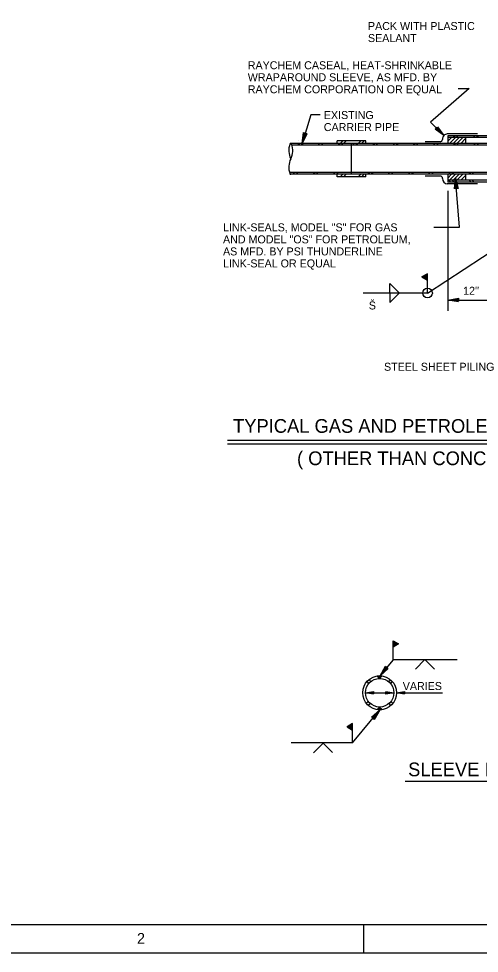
# Model space of a CAD drawing. Extents: x 22422.9 to 22498.9, y 22369.6 to 22415.
# Drawn here: x 22455.11 to 22465.87, y 22369.62 to 22391.43 of the extents above; entities that cross this region are included whole.
import ezdxf

# ---------------------------------------------------------------- set-up
doc = ezdxf.new("R2010")
doc.units = 0
for name, color, linetype in [('Level 1', 7, 'Continuous'), ('Level 10', 7, 'Continuous'), ('Level 2', 7, 'Continuous'), ('Level 3', 7, 'Continuous'), ('Level 4', 7, 'Continuous'), ('Level 7', 7, 'Continuous'), ('Level 8', 7, 'Continuous'), ('Level 9', 7, 'Continuous')]:
    doc.layers.add(name, color=color, linetype=linetype)

msp = doc.modelspace()

# ---------------------------------------------------------------- linework, layer by layer
at = {"layer": 'Level 1'}
for p, q in [((22461.644, 22388.584), (22461.644, 22388.584)), ((22468.13, 22388.696), (22465.13, 22388.696)), ((22468.13, 22388.655), (22465.13, 22388.655)), ((22465.13, 22388.566), (22465.218, 22388.655)), ((22465.166, 22388.514), (22465.307, 22388.655)), ((22465.254, 22388.514), (22465.395, 22388.655)), ((22465.343, 22388.514), (22465.483, 22388.655)), ((22465.431, 22388.514), (22465.546, 22388.629)), ((22465.13, 22387.707), (22465.218, 22387.795)), ((22465.166, 22387.655), (22465.307, 22387.795)), ((22465.254, 22387.655), (22465.395, 22387.795)), ((22465.343, 22387.655), (22465.483, 22387.795)), ((22465.431, 22387.655), (22465.546, 22387.77)), ((22468.13, 22387.655), (22465.13, 22387.655)), ((22468.13, 22387.613), (22465.13, 22387.613)), ((22465.361, 22387.569), (22465.361, 22387.569)), ((22465.13, 22387.412), (22465.13, 22384.613)), ((22465.13, 22384.861), (22466.128, 22384.861)), ((22463.594, 22376.152), (22463.594, 22376.152)), ((22463.287, 22375.919), (22463.243, 22375.964)), ((22463.332, 22375.962), (22463.288, 22376.007)), ((22463.55, 22376.098), (22463.55, 22376.098)), ((22463.747, 22375.96), (22463.791, 22376.005)), ((22463.792, 22375.917), (22463.836, 22375.961)), ((22463.205, 22375.7), (22463.872, 22375.7)), ((22463.205, 22375.7), (22463.205, 22375.7)), ((22463.257, 22375.7), (22463.257, 22375.7)), ((22463.82, 22375.7), (22463.82, 22375.7)), ((22463.872, 22375.7), (22463.872, 22375.7)), ((22463.934, 22375.7), (22465.007, 22375.7)), ((22463.934, 22375.7), (22463.934, 22375.7)), ((22463.986, 22375.7), (22463.986, 22375.7)), ((22463.228, 22375.454), (22463.273, 22375.498)), ((22463.845, 22375.45), (22463.8, 22375.494)), ((22463.271, 22375.408), (22463.315, 22375.452)), ((22463.541, 22375.298), (22463.541, 22375.298)), ((22463.802, 22375.405), (22463.757, 22375.449)), ((22463.497, 22375.245), (22463.497, 22375.245))]:
    msp.add_line(p, q, dxfattribs=at)
msp.add_lwpolyline([(22440.26, 22414.965), (22498.927, 22414.965), (22498.927, 22369.621), (22440.26, 22369.621)], close=True, dxfattribs=at)
for points in [[(22463.392, 22375.669), (22463.205, 22375.7), (22463.392, 22375.731), (22463.392, 22375.678), (22463.257, 22375.7), (22463.384, 22375.721), (22463.384, 22375.687), (22463.307, 22375.7), (22463.376, 22375.711), (22463.376, 22375.697), (22463.359, 22375.7)], [(22463.685, 22375.731), (22463.872, 22375.7), (22463.685, 22375.669), (22463.685, 22375.722), (22463.82, 22375.7), (22463.693, 22375.679), (22463.693, 22375.713), (22463.77, 22375.7), (22463.701, 22375.689), (22463.701, 22375.703), (22463.718, 22375.7)], [(22464.121, 22375.669), (22463.934, 22375.7), (22464.121, 22375.731), (22464.121, 22375.678), (22463.986, 22375.7), (22464.113, 22375.721), (22464.113, 22375.687), (22464.036, 22375.7), (22464.105, 22375.711), (22464.105, 22375.697), (22464.088, 22375.7)]]:
    msp.add_lwpolyline(points, dxfattribs=at)
for centre, radius, start, end in [((22461.852, 22388.35), 0.436, 159.8064, 206.6071), ((22461.463, 22388.493), 0.0213, 20.1936, 159.8064), ((22461.074, 22388.35), 0.436, 333.3929, 20.1936), ((22461.852, 22387.96), 0.436, 153.3929, 200.1919), ((22461.463, 22387.817), 0.0213, 200.3155, 270)]:
    msp.add_arc(centre, radius, start, end, dxfattribs=at)
at = {"layer": 'Level 10'}
for p, q in [((22464.656, 22385.026), (22467.63, 22386.967)), ((22464.656, 22385.476), (22464.526, 22385.401)), ((22464.526, 22385.401), (22464.656, 22385.448)), ((22464.526, 22385.401), (22464.656, 22385.422)), ((22464.526, 22385.401), (22464.655, 22385.326)), ((22464.526, 22385.401), (22464.649, 22385.394)), ((22464.526, 22385.401), (22464.653, 22385.371)), ((22464.526, 22385.401), (22464.656, 22385.35)), ((22464.656, 22385.026), (22464.656, 22385.476)), ((22463.777, 22385.249), (22464.001, 22385.025)), ((22463.777, 22385.024), (22463.777, 22385.249)), ((22464.656, 22385.026), (22463.155, 22385.026)), ((22463.777, 22385.028), (22463.777, 22384.803)), ((22463.777, 22384.803), (22464.001, 22385.027)), ((22459.986, 22381.589), (22476.306, 22381.589)), ((22459.986, 22381.505), (22476.327, 22381.505)), ((22463.851, 22376.464), (22463.851, 22376.914)), ((22463.851, 22376.914), (22463.981, 22376.839)), ((22463.981, 22376.839), (22463.851, 22376.885)), ((22463.981, 22376.839), (22463.851, 22376.86)), ((22463.981, 22376.839), (22463.851, 22376.764)), ((22463.981, 22376.839), (22463.851, 22376.788)), ((22463.981, 22376.839), (22463.853, 22376.809)), ((22463.981, 22376.839), (22463.858, 22376.832)), ((22463.55, 22376.098), (22463.851, 22376.464)), ((22463.846, 22376.472), (22465.347, 22376.472)), ((22464.597, 22376.472), (22464.375, 22376.25)), ((22464.596, 22376.472), (22464.82, 22376.248)), ((22462.907, 22374.529), (22463.541, 22375.298)), ((22462.907, 22374.979), (22462.777, 22374.904)), ((22462.777, 22374.904), (22462.907, 22374.951)), ((22462.777, 22374.904), (22462.907, 22374.925)), ((22462.777, 22374.904), (22462.907, 22374.829)), ((22462.777, 22374.904), (22462.9, 22374.897)), ((22462.777, 22374.904), (22462.905, 22374.874)), ((22462.777, 22374.904), (22462.907, 22374.853)), ((22462.907, 22374.529), (22462.907, 22374.798)), ((22462.907, 22374.529), (22461.469, 22374.529)), ((22462.218, 22374.525), (22461.995, 22374.301)), ((22462.218, 22374.524), (22462.439, 22374.303)), ((22464.137, 22373.635), (22472.537, 22373.635)), ((22463.167, 22369.621), (22463.167, 22370.293))]:
    msp.add_line(p, q, dxfattribs=at)
for points in [[(22463.74, 22376.264), (22463.55, 22376.098), (22463.676, 22376.317), (22463.731, 22376.272), (22463.594, 22376.152), (22463.68, 22376.3), (22463.715, 22376.271), (22463.636, 22376.203), (22463.683, 22376.283), (22463.698, 22376.271), (22463.68, 22376.257)], [(22463.35, 22375.132), (22463.541, 22375.298), (22463.414, 22375.079), (22463.36, 22375.124), (22463.497, 22375.245), (22463.411, 22375.096), (22463.376, 22375.125), (22463.454, 22375.193), (22463.407, 22375.113), (22463.393, 22375.125), (22463.41, 22375.14)]]:
    msp.add_lwpolyline(points, dxfattribs=at)
msp.add_circle((22464.656, 22385.026), 0.113, dxfattribs=at)
at = {"layer": 'Level 2'}
for p, q in [((22465.628, 22389.797), (22464.728, 22389.011)), ((22465.369, 22389.797), (22465.628, 22389.797)), ((22464.728, 22389.011), (22465.038, 22388.7)), ((22462.546, 22388.514), (22462.546, 22388.577)), ((22463.213, 22388.577), (22462.546, 22388.577)), ((22463.213, 22388.514), (22463.213, 22388.577)), ((22465.13, 22388.696), (22465.13, 22388.514)), ((22465.546, 22388.655), (22465.546, 22388.514)), ((22468.13, 22388.514), (22461.463, 22388.514)), ((22468.13, 22388.472), (22461.492, 22388.472)), ((22462.88, 22387.795), (22462.88, 22388.514)), ((22468.13, 22387.837), (22461.434, 22387.837)), ((22468.13, 22387.795), (22461.464, 22387.795)), ((22462.546, 22387.733), (22462.546, 22387.795)), ((22463.213, 22387.733), (22462.546, 22387.733)), ((22463.213, 22387.733), (22463.213, 22387.795)), ((22465.13, 22387.795), (22465.13, 22387.613)), ((22465.546, 22387.795), (22465.546, 22387.655)), ((22463.538, 22376.034), (22463.48, 22376.092)), ((22463.538, 22376.034), (22463.596, 22376.092)), ((22463.538, 22375.367), (22463.48, 22375.309)), ((22463.538, 22375.367), (22463.596, 22375.309))]:
    msp.add_line(p, q, dxfattribs=at)
for points in [[(22462.151, 22389.185), (22461.932, 22389.185), (22461.726, 22388.517)], [(22464.891, 22388.906), (22465.038, 22388.7), (22464.832, 22388.848), (22464.882, 22388.898), (22464.989, 22388.75), (22464.849, 22388.85), (22464.881, 22388.882), (22464.942, 22388.797), (22464.866, 22388.851), (22464.88, 22388.865), (22464.893, 22388.846)], [(22461.839, 22388.743), (22461.726, 22388.517), (22461.76, 22388.767), (22461.828, 22388.746), (22461.747, 22388.583), (22461.77, 22388.753), (22461.813, 22388.74), (22461.766, 22388.647), (22461.779, 22388.739), (22461.797, 22388.733), (22461.787, 22388.713)], [(22464.801, 22386.562), (22465.4, 22386.562), (22465.309, 22387.709)], [(22465.287, 22387.457), (22465.309, 22387.709), (22465.37, 22387.464), (22465.299, 22387.458), (22465.314, 22387.64), (22465.356, 22387.473), (22465.31, 22387.47), (22465.32, 22387.574), (22465.342, 22387.483), (22465.323, 22387.482), (22465.325, 22387.504)], [(22465.379, 22384.82), (22465.13, 22384.861), (22465.379, 22384.903), (22465.379, 22384.832), (22465.199, 22384.861), (22465.368, 22384.889), (22465.368, 22384.844), (22465.266, 22384.861), (22465.358, 22384.876), (22465.358, 22384.857), (22465.335, 22384.861)], [(22463.481, 22376.091), (22463.595, 22376.091)], [(22463.492, 22376.08), (22463.585, 22376.08)], [(22463.502, 22376.07), (22463.575, 22376.07)], [(22463.512, 22376.059), (22463.564, 22376.059)], [(22463.523, 22376.049), (22463.554, 22376.049)], [(22463.533, 22376.039), (22463.543, 22376.039)], [(22463.488, 22375.317), (22463.588, 22375.317)], [(22463.499, 22375.327), (22463.578, 22375.327)], [(22463.5, 22375.306), (22463.578, 22375.306)], [(22463.509, 22375.338), (22463.567, 22375.338)], [(22463.519, 22375.348), (22463.557, 22375.348)], [(22463.53, 22375.359), (22463.547, 22375.359)]]:
    msp.add_lwpolyline(points, dxfattribs=at)
for radius in [0.396, 0.333]:
    msp.add_circle((22463.538, 22375.7), radius, dxfattribs=at)
at = {"layer": 'Level 3'}
for p, q in [((22463.538, 22376.034), (22463.538, 22376.034)), ((22463.538, 22375.7), (22463.538, 22375.7))]:
    msp.add_line(p, q, dxfattribs=at)
at = {"layer": 'Level 4'}
msp.add_line((22462.907, 22374.798), (22462.907, 22374.979), dxfattribs=at)
at = {"layer": 'Level 7'}
for p, q in [((22465.823, 22388.738), (22465.119, 22388.738)), ((22464.949, 22388.556), (22464.602, 22388.556)), ((22464.949, 22387.754), (22464.602, 22387.754)), ((22465.823, 22387.571), (22465.119, 22387.571)), ((22464.597, 22376.472), (22464.597, 22376.472)), ((22462.217, 22374.525), (22462.218, 22374.524))]:
    msp.add_line(p, q, dxfattribs=at)
for centre, radius, start, end in [((22464.949, 22388.611), 0.0555, 270, 0), ((22465.126, 22388.617), 0.121, 92.9001, 182.9001), ((22464.949, 22387.696), 0.0581, 0, 90), ((22465.126, 22387.689), 0.118, 177.036, 267.036)]:
    msp.add_arc(centre, radius, start, end, dxfattribs=at)
at = {"layer": 'Level 8'}
for p, q in [((22461.747, 22388.583), (22461.747, 22388.583)), ((22464.989, 22388.75), (22464.989, 22388.75)), ((22465.038, 22388.7), (22465.038, 22388.7)), ((22461.726, 22388.517), (22461.726, 22388.517)), ((22465.309, 22387.709), (22465.309, 22387.709)), ((22465.314, 22387.64), (22465.314, 22387.64)), ((22465.13, 22384.861), (22465.13, 22384.861)), ((22465.199, 22384.861), (22465.199, 22384.861))]:
    msp.add_line(p, q, dxfattribs=at)
for points in [[(22462.68, 22388.577), (22462.617, 22388.514)], [(22462.76, 22388.577), (22462.697, 22388.514)], [(22463.102, 22388.577), (22463.039, 22388.514)], [(22463.179, 22388.577), (22463.117, 22388.514)], [(22465.292, 22388.66), (22465.256, 22388.696)], [(22465.368, 22388.66), (22465.331, 22388.696)], [(22465.764, 22388.66), (22465.727, 22388.696)], [(22465.839, 22388.66), (22465.803, 22388.696)], [(22461.672, 22388.472), (22461.63, 22388.514)], [(22461.748, 22388.472), (22461.706, 22388.514)], [(22462.143, 22388.472), (22462.102, 22388.514)], [(22462.219, 22388.472), (22462.177, 22388.514)], [(22462.615, 22388.472), (22462.573, 22388.514)], [(22462.69, 22388.472), (22462.649, 22388.514)], [(22462.952, 22388.472), (22462.911, 22388.514)], [(22463.026, 22388.472), (22462.984, 22388.514)], [(22463.422, 22388.472), (22463.38, 22388.514)], [(22463.498, 22388.472), (22463.456, 22388.514)], [(22463.894, 22388.472), (22463.852, 22388.514)], [(22463.969, 22388.472), (22463.927, 22388.514)], [(22464.365, 22388.472), (22464.323, 22388.514)], [(22464.44, 22388.472), (22464.399, 22388.514)], [(22464.836, 22388.472), (22464.795, 22388.514)], [(22464.912, 22388.472), (22464.87, 22388.514)], [(22465.308, 22388.472), (22465.266, 22388.514)], [(22465.383, 22388.472), (22465.342, 22388.514)], [(22465.779, 22388.472), (22465.738, 22388.514)], [(22465.855, 22388.472), (22465.813, 22388.514)], [(22461.559, 22387.795), (22461.517, 22387.837)], [(22461.635, 22387.795), (22461.593, 22387.837)], [(22462.031, 22387.795), (22461.989, 22387.837)], [(22462.106, 22387.795), (22462.064, 22387.837)], [(22462.502, 22387.795), (22462.46, 22387.837)], [(22462.577, 22387.795), (22462.536, 22387.837)], [(22462.68, 22387.795), (22462.617, 22387.733)], [(22462.76, 22387.795), (22462.697, 22387.733)], [(22463.102, 22387.795), (22463.039, 22387.733)], [(22463.179, 22387.795), (22463.117, 22387.733)], [(22463.308, 22387.795), (22463.266, 22387.837)], [(22463.383, 22387.795), (22463.342, 22387.837)], [(22463.779, 22387.795), (22463.738, 22387.837)], [(22463.855, 22387.795), (22463.813, 22387.837)], [(22464.251, 22387.795), (22464.209, 22387.837)], [(22464.326, 22387.795), (22464.285, 22387.837)], [(22464.722, 22387.795), (22464.681, 22387.837)], [(22464.798, 22387.795), (22464.756, 22387.837)], [(22465.194, 22387.795), (22465.152, 22387.837)], [(22465.269, 22387.795), (22465.227, 22387.837)], [(22465.665, 22387.795), (22465.623, 22387.837)], [(22465.74, 22387.795), (22465.699, 22387.837)], [(22465.194, 22387.623), (22465.168, 22387.649)], [(22465.269, 22387.623), (22465.243, 22387.649)], [(22465.665, 22387.623), (22465.639, 22387.649)], [(22465.74, 22387.623), (22465.714, 22387.649)]]:
    msp.add_lwpolyline(points, dxfattribs=at)
at = {"layer": 'Level 9'}
msp.add_line((22442.26, 22370.293), (22494.591, 22370.293), dxfattribs=at)

# ---------------------------------------------------------------- texts
at = {"layer": 'Level 1'}
msp.add_text('2', height=0.25, dxfattribs=at).set_placement((22457.871, 22369.845))
at = {"layer": 'Level 3'}
for s, p in [('TYPICAL GAS AND PETROLEUM PIPES THRU STEEL SHEET PILING', (22460.115, 22381.764)), ('( OTHER THAN CONCRETE COATED PIPE, OPTION 1 )', (22461.608, 22381.01)), ('SLEEVE INSTALLATION IN HALVES', (22464.203, 22373.752))]:
    msp.add_text(s, height=0.32, dxfattribs=at).set_placement(p)
at = {"layer": 'Level 4'}
for s, height, p in [('PACK WITH PLASTIC', 0.18667, (22463.265, 22391.161)), ('SEALANT', 0.1867, (22463.265, 22390.88)), ('RAYCHEM CASEAL, HEAT-SHRINKABLE', 0.18667, (22460.458, 22390.246)), ('WRAPAROUND SLEEVE, AS MFD. BY', 0.18667, (22460.458, 22389.966)), ('RAYCHEM CORPORATION OR EQUAL', 0.18667, (22460.458, 22389.685)), ('EXISTING', 0.1867, (22462.234, 22389.084)), ('CARRIER PIPE', 0.18667, (22462.234, 22388.804)), ('LINK-SEALS, MODEL "S" FOR GAS', 0.18667, (22459.88, 22386.464)), ('AND MODEL "OS" FOR PETROLEUM,', 0.18667, (22459.88, 22386.184)), ('AS MFD. BY PSI THUNDERLINE', 0.18667, (22459.88, 22385.903)), ('LINK-SEAL OR EQUAL', 0.18667, (22459.88, 22385.623)), ("12''", 0.1867, (22465.488, 22384.985)), ('Š', 0.187, (22463.285, 22384.642)), ('STEEL SHEET PILING', 0.18667, (22463.64, 22383.212)), ('VARIES', 0.1867, (22464.078, 22375.763))]:
    msp.add_text(s, height=height, dxfattribs=at).set_placement(p)

doc.saveas('drawing.dxf')
